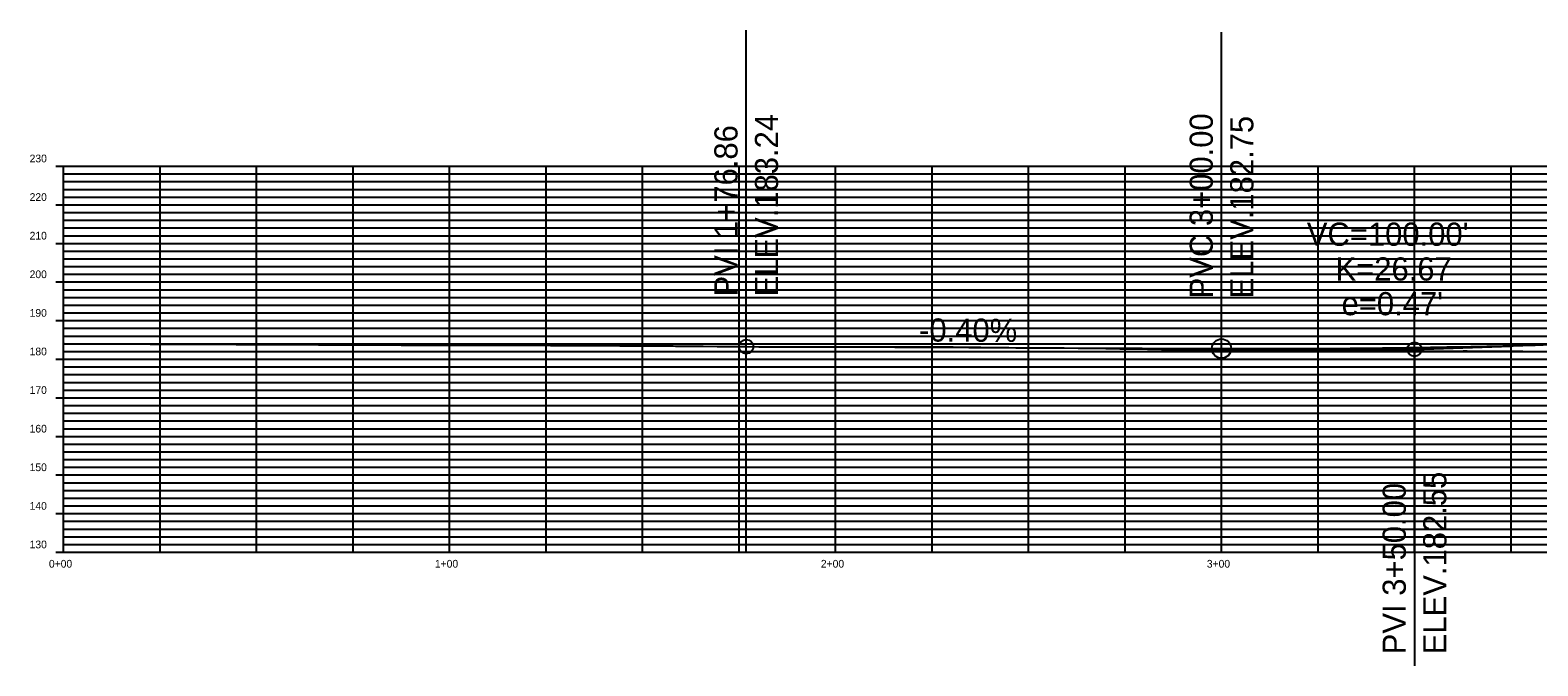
# Model space of a CAD drawing. Extents: x 1405440 to 1409538, y 1842123 to 1843178.
# Drawn here: x 1408721.6 to 1409112.2, y 1843010.4 to 1843175.1 of the extents above; entities that cross this region are included whole.
import ezdxf

# ---------------------------------------------------------------- set-up
doc = ezdxf.new("R2010")
doc.units = 0
for name, color, linetype in [('63', 7, 'Continuous'), ('R_Axis_Annotation', 7, 'Continuous'), ('R_Exist Surface', 7, 'Continuous'), ('R_Grid Annot', 7, 'Continuous'), ('R_Grid_Minor', 7, 'Continuous'), ('R_SFHA', 7, 'Continuous'), ('R_Vert Alg', 7, 'Continuous'), ('R_Vert Alg Annot', 7, 'Continuous')]:
    doc.layers.add(name, color=color, linetype=linetype)

msp = doc.modelspace()

# ---------------------------------------------------------------- linework, layer by layer
for p, q in [((1408730.23, 1843039.81), (1408730.23, 1843139.81)), ((1408730.23, 1843139.81), (1409530.23, 1843139.81)), ((1408730.23, 1843139.81), (1409530.23, 1843139.81)), ((1408830.23, 1843039.81), (1408830.23, 1843139.81)), ((1408930.23, 1843039.81), (1408930.23, 1843139.81)), ((1409030.23, 1843039.81), (1409030.23, 1843139.81)), ((1408730.23, 1843129.81), (1409530.23, 1843129.81)), ((1408730.23, 1843119.81), (1409530.23, 1843119.81)), ((1408730.23, 1843109.81), (1409530.23, 1843109.81)), ((1408730.23, 1843099.81), (1409530.23, 1843099.81)), ((1408730.23, 1843089.81), (1409530.23, 1843089.81)), ((1408730.23, 1843079.81), (1409530.23, 1843079.81)), ((1408730.23, 1843069.81), (1409530.23, 1843069.81)), ((1408730.23, 1843059.81), (1409530.23, 1843059.81)), ((1408730.23, 1843049.81), (1409530.23, 1843049.81)), ((1408730.23, 1843039.81), (1409530.23, 1843039.81))]:
    msp.add_line(p, q)
at = {"layer": 'R_Exist Surface'}
msp.add_lwpolyline([(1408730.23, 1843093.85), (1408730.49, 1843093.84), (1408742.5, 1843093.79), (1408752.7, 1843093.74), (1408763.82, 1843093.68), (1408774.9, 1843093.63), (1408785.71, 1843093.59), (1408796.3, 1843093.54), (1408807.46, 1843093.5), (1408817.7, 1843093.45), (1408827.54, 1843093.46), (1408828.63, 1843093.46), (1408831.14, 1843093.45), (1408834.74, 1843093.45), (1408838.34, 1843093.44), (1408839.88, 1843093.44), (1408841.94, 1843093.43), (1408845.54, 1843093.43), (1408849.14, 1843093.42), (1408850.48, 1843093.41), (1408852.74, 1843093.4), (1408856.34, 1843093.39), (1408859.93, 1843093.37), (1408862.13, 1843093.35), (1408863.53, 1843093.35), (1408867.13, 1843093.34), (1408870.14, 1843093.34), (1408870.73, 1843093.33), (1408874.33, 1843093.31), (1408877.93, 1843093.29), (1408881.53, 1843093.27), (1408883.29, 1843093.26), (1408885.13, 1843093.25), (1408888.14, 1843093.23), (1408888.73, 1843093.22), (1408892.32, 1843093.19), (1408895.92, 1843093.16), (1408899.52, 1843093.12), (1408903.12, 1843093.08), (1408904.47, 1843093.07), (1408904.72, 1843093.07), (1408906.72, 1843093.06), (1408907.07, 1843093.06), (1408910.32, 1843093.05), (1408913.92, 1843093.05), (1408917.52, 1843093.04), (1408918.79, 1843093.04), (1408921.11, 1843093.04), (1408923.92, 1843093.04), (1408924.71, 1843093.04), (1408928.31, 1843093.03), (1408931.91, 1843093.02), (1408932.58, 1843093.02), (1408935.51, 1843093.02), (1408939.11, 1843093.01), (1408941.73, 1843093.01), (1408942.71, 1843093.01), (1408946.31, 1843093), (1408949.91, 1843092.99), (1408953.5, 1843092.98), (1408955.62, 1843092.98), (1408957.1, 1843092.98), (1408958.65, 1843092.98), (1408960.7, 1843092.97), (1408962.6, 1843092.96), (1408964.3, 1843092.94), (1408967.9, 1843092.9), (1408971.5, 1843092.85), (1408973.95, 1843092.82), (1408975.1, 1843092.81), (1408976.95, 1843092.78), (1408978.7, 1843092.77), (1408982.3, 1843092.76), (1408985.89, 1843092.73), (1408989.49, 1843092.71), (1408993.09, 1843092.68), (1408995.85, 1843092.65), (1408996.69, 1843092.64), (1409000.29, 1843092.57), (1409001.46, 1843092.55), (1409003.89, 1843092.52), (1409007.49, 1843092.47), (1409011.09, 1843092.41), (1409014.69, 1843092.35), (1409017.5, 1843092.31), (1409018.28, 1843092.31), (1409021.88, 1843092.31), (1409025.48, 1843092.32), (1409026.45, 1843092.31), (1409029.08, 1843092.31), (1409032.04, 1843092.3), (1409032.68, 1843092.3), (1409036.28, 1843092.28), (1409038.26, 1843092.27), (1409039.88, 1843092.26), (1409043.48, 1843092.24), (1409046.59, 1843092.22), (1409047.08, 1843092.22), (1409050.67, 1843092.19), (1409053.81, 1843092.15), (1409054.27, 1843092.15), (1409057.87, 1843092.11), (1409061.1, 1843092.08), (1409061.47, 1843092.07), (1409065.07, 1843092.02), (1409068.67, 1843091.96), (1409070.78, 1843091.93), (1409072.27, 1843091.91), (1409075.48, 1843091.85), (1409075.87, 1843091.86), (1409079.28, 1843091.92), (1409079.46, 1843091.92), (1409083.06, 1843091.91), (1409086.66, 1843091.9), (1409088.48, 1843091.9), (1409090.26, 1843091.92), (1409092.87, 1843091.95), (1409093.86, 1843091.95), (1409097.46, 1843091.92), (1409101.06, 1843091.89), (1409101.52, 1843091.89), (1409104.66, 1843091.91), (1409105.78, 1843091.92), (1409108.26, 1843091.89), (1409111.85, 1843091.83), (1409114.66, 1843091.79)], dxfattribs=at)
at = {"layer": 'R_Grid Annot'}
for p, q in [((1408728.23, 1843139.81), (1408730.23, 1843139.81)), ((1408728.23, 1843139.81), (1408730.23, 1843139.81)), ((1408730.23, 1843137.81), (1408733.23, 1843137.81)), ((1408730.23, 1843135.81), (1408733.23, 1843135.81)), ((1408730.23, 1843133.81), (1408733.23, 1843133.81)), ((1408728.23, 1843129.81), (1408730.23, 1843129.81)), ((1408730.23, 1843131.81), (1408733.23, 1843131.81)), ((1408730.23, 1843127.81), (1408733.23, 1843127.81)), ((1408730.23, 1843125.81), (1408733.23, 1843125.81)), ((1408730.23, 1843123.81), (1408733.23, 1843123.81)), ((1408730.23, 1843121.81), (1408733.23, 1843121.81)), ((1408728.23, 1843119.81), (1408730.23, 1843119.81)), ((1408730.23, 1843117.81), (1408733.23, 1843117.81)), ((1408730.23, 1843115.81), (1408733.23, 1843115.81)), ((1408730.23, 1843113.81), (1408733.23, 1843113.81)), ((1408730.23, 1843111.81), (1408733.23, 1843111.81)), ((1408728.23, 1843109.81), (1408730.23, 1843109.81)), ((1408730.23, 1843107.81), (1408733.23, 1843107.81)), ((1408730.23, 1843105.81), (1408733.23, 1843105.81)), ((1408730.23, 1843103.81), (1408733.23, 1843103.81)), ((1408728.23, 1843099.81), (1408730.23, 1843099.81)), ((1408730.23, 1843101.81), (1408733.23, 1843101.81)), ((1408730.23, 1843097.81), (1408733.23, 1843097.81)), ((1408730.23, 1843095.81), (1408733.23, 1843095.81)), ((1408730.23, 1843093.81), (1408733.23, 1843093.81)), ((1408730.23, 1843091.81), (1408733.23, 1843091.81)), ((1408728.23, 1843089.81), (1408730.23, 1843089.81)), ((1408730.23, 1843087.81), (1408733.23, 1843087.81)), ((1408730.23, 1843085.81), (1408733.23, 1843085.81)), ((1408730.23, 1843083.81), (1408733.23, 1843083.81)), ((1408728.23, 1843079.81), (1408730.23, 1843079.81)), ((1408730.23, 1843081.81), (1408733.23, 1843081.81)), ((1408730.23, 1843077.81), (1408733.23, 1843077.81)), ((1408730.23, 1843075.81), (1408733.23, 1843075.81)), ((1408730.23, 1843073.81), (1408733.23, 1843073.81)), ((1408730.23, 1843071.81), (1408733.23, 1843071.81)), ((1408728.23, 1843069.81), (1408730.23, 1843069.81)), ((1408730.23, 1843067.81), (1408733.23, 1843067.81)), ((1408730.23, 1843065.81), (1408733.23, 1843065.81)), ((1408730.23, 1843063.81), (1408733.23, 1843063.81)), ((1408728.23, 1843059.81), (1408730.23, 1843059.81)), ((1408730.23, 1843061.81), (1408733.23, 1843061.81)), ((1408730.23, 1843057.81), (1408733.23, 1843057.81)), ((1408730.23, 1843055.81), (1408733.23, 1843055.81)), ((1408730.23, 1843053.81), (1408733.23, 1843053.81)), ((1408730.23, 1843051.81), (1408733.23, 1843051.81)), ((1408728.23, 1843049.81), (1408730.23, 1843049.81)), ((1408730.23, 1843047.81), (1408733.23, 1843047.81)), ((1408730.23, 1843045.81), (1408733.23, 1843045.81)), ((1408730.23, 1843043.81), (1408733.23, 1843043.81)), ((1408728.23, 1843039.81), (1408730.23, 1843039.81)), ((1408730.23, 1843041.81), (1408733.23, 1843041.81))]:
    msp.add_line(p, q, dxfattribs=at)
at = {"layer": 'R_Grid_Minor'}
for p, q in [((1408730.23, 1843137.81), (1409530.23, 1843137.81)), ((1408755.23, 1843039.81), (1408755.23, 1843139.81)), ((1408780.23, 1843039.81), (1408780.23, 1843139.81)), ((1408805.23, 1843039.81), (1408805.23, 1843139.81)), ((1408855.23, 1843039.81), (1408855.23, 1843139.81)), ((1408880.23, 1843039.81), (1408880.23, 1843139.81)), ((1408905.23, 1843039.81), (1408905.23, 1843139.81)), ((1408955.23, 1843039.81), (1408955.23, 1843139.81)), ((1408980.23, 1843039.81), (1408980.23, 1843139.81)), ((1409005.23, 1843039.81), (1409005.23, 1843139.81)), ((1409055.23, 1843039.81), (1409055.23, 1843139.81)), ((1409080.23, 1843039.81), (1409080.23, 1843139.81)), ((1409105.23, 1843039.81), (1409105.23, 1843139.81)), ((1408730.23, 1843135.81), (1409530.23, 1843135.81)), ((1408730.23, 1843133.81), (1409530.23, 1843133.81)), ((1408730.23, 1843131.81), (1409530.23, 1843131.81)), ((1408730.23, 1843127.81), (1409530.23, 1843127.81)), ((1408730.23, 1843125.81), (1409530.23, 1843125.81)), ((1408730.23, 1843123.81), (1409530.23, 1843123.81)), ((1408730.23, 1843121.81), (1409530.23, 1843121.81)), ((1408730.23, 1843117.81), (1409530.23, 1843117.81)), ((1408730.23, 1843115.81), (1409530.23, 1843115.81)), ((1408730.23, 1843113.81), (1409530.23, 1843113.81)), ((1408730.23, 1843111.81), (1409530.23, 1843111.81)), ((1408730.23, 1843107.81), (1409530.23, 1843107.81)), ((1408730.23, 1843105.81), (1409530.23, 1843105.81)), ((1408730.23, 1843103.81), (1409530.23, 1843103.81)), ((1408730.23, 1843101.81), (1409530.23, 1843101.81)), ((1408730.23, 1843097.81), (1409530.23, 1843097.81)), ((1408730.23, 1843095.81), (1409530.23, 1843095.81)), ((1408730.23, 1843093.81), (1409530.23, 1843093.81)), ((1408730.23, 1843091.81), (1409530.23, 1843091.81)), ((1408730.23, 1843087.81), (1409530.23, 1843087.81)), ((1408730.23, 1843085.81), (1409530.23, 1843085.81)), ((1408730.23, 1843083.81), (1409530.23, 1843083.81)), ((1408730.23, 1843081.81), (1409530.23, 1843081.81)), ((1408730.23, 1843077.81), (1409530.23, 1843077.81)), ((1408730.23, 1843075.81), (1409530.23, 1843075.81)), ((1408730.23, 1843073.81), (1409530.23, 1843073.81)), ((1408730.23, 1843071.81), (1409530.23, 1843071.81)), ((1408730.23, 1843067.81), (1409530.23, 1843067.81)), ((1408730.23, 1843065.81), (1409530.23, 1843065.81)), ((1408730.23, 1843063.81), (1409530.23, 1843063.81)), ((1408730.23, 1843061.81), (1409530.23, 1843061.81)), ((1408730.23, 1843057.81), (1409530.23, 1843057.81)), ((1408730.23, 1843055.81), (1409530.23, 1843055.81)), ((1408730.23, 1843053.81), (1409530.23, 1843053.81)), ((1408730.23, 1843051.81), (1409530.23, 1843051.81)), ((1408730.23, 1843047.81), (1409530.23, 1843047.81)), ((1408730.23, 1843045.81), (1409530.23, 1843045.81)), ((1408730.23, 1843043.81), (1409530.23, 1843043.81)), ((1408730.23, 1843041.81), (1409530.23, 1843041.81))]:
    msp.add_line(p, q, dxfattribs=at)
at = {"layer": 'R_SFHA'}
for p, q in [((1408907.09, 1843039.81), (1408907.09, 1843139.81)), ((1409180.23, 1843095.71), (1409080.23, 1843092.36)), ((1408907.09, 1843093.06), (1409080.23, 1843092.36))]:
    msp.add_line(p, q, dxfattribs=at)
at = {"layer": 'R_Vert Alg'}
msp.add_line((1408907.09, 1843093.06), (1409030.23, 1843092.56), dxfattribs=at)
msp.add_lwpolyline([(1409030.23, 1843092.56), (1409032.32, 1843092.56), (1409034.4, 1843092.55), (1409036.48, 1843092.55), (1409038.57, 1843092.54), (1409040.65, 1843092.54), (1409042.73, 1843092.54), (1409044.82, 1843092.54), (1409046.9, 1843092.55), (1409048.98, 1843092.55), (1409051.07, 1843092.56), (1409053.15, 1843092.57), (1409055.23, 1843092.58), (1409057.32, 1843092.59), (1409059.4, 1843092.61), (1409061.48, 1843092.62), (1409063.57, 1843092.64), (1409065.65, 1843092.66), (1409067.73, 1843092.68), (1409069.82, 1843092.7), (1409071.9, 1843092.72), (1409073.98, 1843092.75), (1409076.07, 1843092.77), (1409078.15, 1843092.8), (1409082.32, 1843092.86), (1409084.4, 1843092.9), (1409086.48, 1843092.93), (1409088.57, 1843092.97), (1409090.65, 1843093.01), (1409092.73, 1843093.05), (1409094.82, 1843093.09), (1409096.9, 1843093.13), (1409098.98, 1843093.17), (1409101.07, 1843093.22), (1409103.15, 1843093.27), (1409105.23, 1843093.32), (1409107.32, 1843093.37), (1409109.4, 1843093.42), (1409111.48, 1843093.48), (1409113.57, 1843093.53)], dxfattribs=at)
at = {"layer": 'R_Vert Alg Annot'}
for p, q in [((1408907.09, 1843103.06), (1408907.09, 1843175.06)), ((1409030.23, 1843102.56), (1409030.23, 1843174.56)), ((1408907.09, 1843093.06), (1408907.09, 1843103.06)), ((1409030.23, 1843092.56), (1409030.23, 1843102.56)), ((1409055.23, 1843092.46), (1409080.23, 1843092.36)), ((1409080.23, 1843092.36), (1409105.23, 1843093.2)), ((1409080.23, 1843092.36), (1409080.23, 1843082.36)), ((1409080.23, 1843082.36), (1409080.23, 1843010.36))]:
    msp.add_line(p, q, dxfattribs=at)
for centre, radius in [((1408907.09, 1843093.06), 1.85), ((1409030.23, 1843092.56), 2.5), ((1409080.23, 1843092.36), 1.85)]:
    msp.add_circle(centre, radius, dxfattribs=at)

# ---------------------------------------------------------------- texts
at = {"layer": '63'}
msp.add_text('-', height=0.0001, dxfattribs=at).set_placement((1408730.23, 1843039.81))
at = {"layer": 'R_Axis_Annotation'}
for s, p in [('230', (1408721.43, 1843140.81)), ('230', (1408721.43, 1843140.81)), ('220', (1408721.43, 1843130.81)), ('210', (1408721.43, 1843120.81)), ('200', (1408721.43, 1843110.81)), ('190', (1408721.43, 1843100.81)), ('180', (1408721.43, 1843090.81)), ('170', (1408721.43, 1843080.81)), ('160', (1408721.43, 1843070.81)), ('150', (1408721.43, 1843060.81)), ('140', (1408721.43, 1843050.81)), ('130', (1408721.43, 1843040.81)), ('0+00', (1408726.43, 1843035.81)), ('1+00', (1408826.43, 1843035.81)), ('2+00', (1408926.43, 1843035.81)), ('3+00', (1409026.43, 1843035.81))]:
    msp.add_text(s, height=2, dxfattribs=at).set_placement(p)
at = {"layer": 'R_Vert Alg Annot'}
for s, rotation, p in [('ELEV.183.24', 90, (1408915.34, 1843106.06)), ('PVC 3+00.00', 90, (1409027.98, 1843105.56)), ('PVI 1+76.86', 90, (1408904.84, 1843106.06)), ('ELEV.182.75', 90, (1409038.48, 1843105.56)), ('-0.40%', 359.7708, (1408951.87, 1843094.38)), ('ELEV.182.55', 90, (1409088.48, 1843013.36)), ('PVI 3+50.00', 90, (1409077.98, 1843013.36))]:
    msp.add_text(s, height=6, rotation=rotation, dxfattribs=at).set_placement(p)
for s, p in [("VC=100.00'", (1409052.33, 1843119.19)), ('K=26.67', (1409059.76, 1843110.19)), ("e=0.47'", (1409061.33, 1843101.19))]:
    msp.add_text(s, height=6, dxfattribs=at).set_placement(p)

doc.saveas('drawing.dxf')
